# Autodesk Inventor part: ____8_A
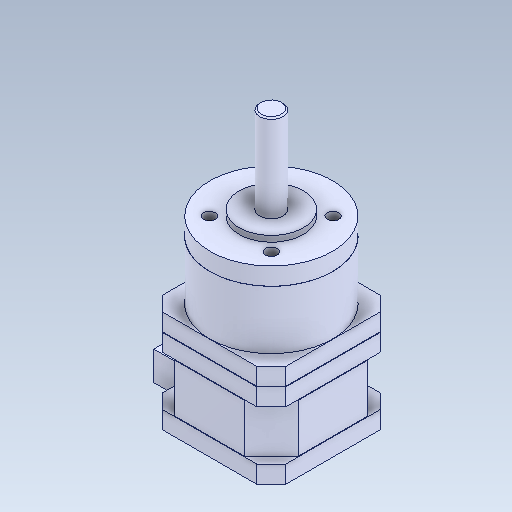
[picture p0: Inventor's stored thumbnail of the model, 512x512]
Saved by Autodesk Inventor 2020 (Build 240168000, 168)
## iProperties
Created: 2017-09
Part Number: ____8_A
Material: Générique
Document SubType Name: Modeling
Designer: bruno
Density: 1 g/cm^3
Appearance: Par défaut
Author: bruno
Sending System: SolidWorks 2016
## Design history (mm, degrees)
feature "Importée1"
node "Solide1"
